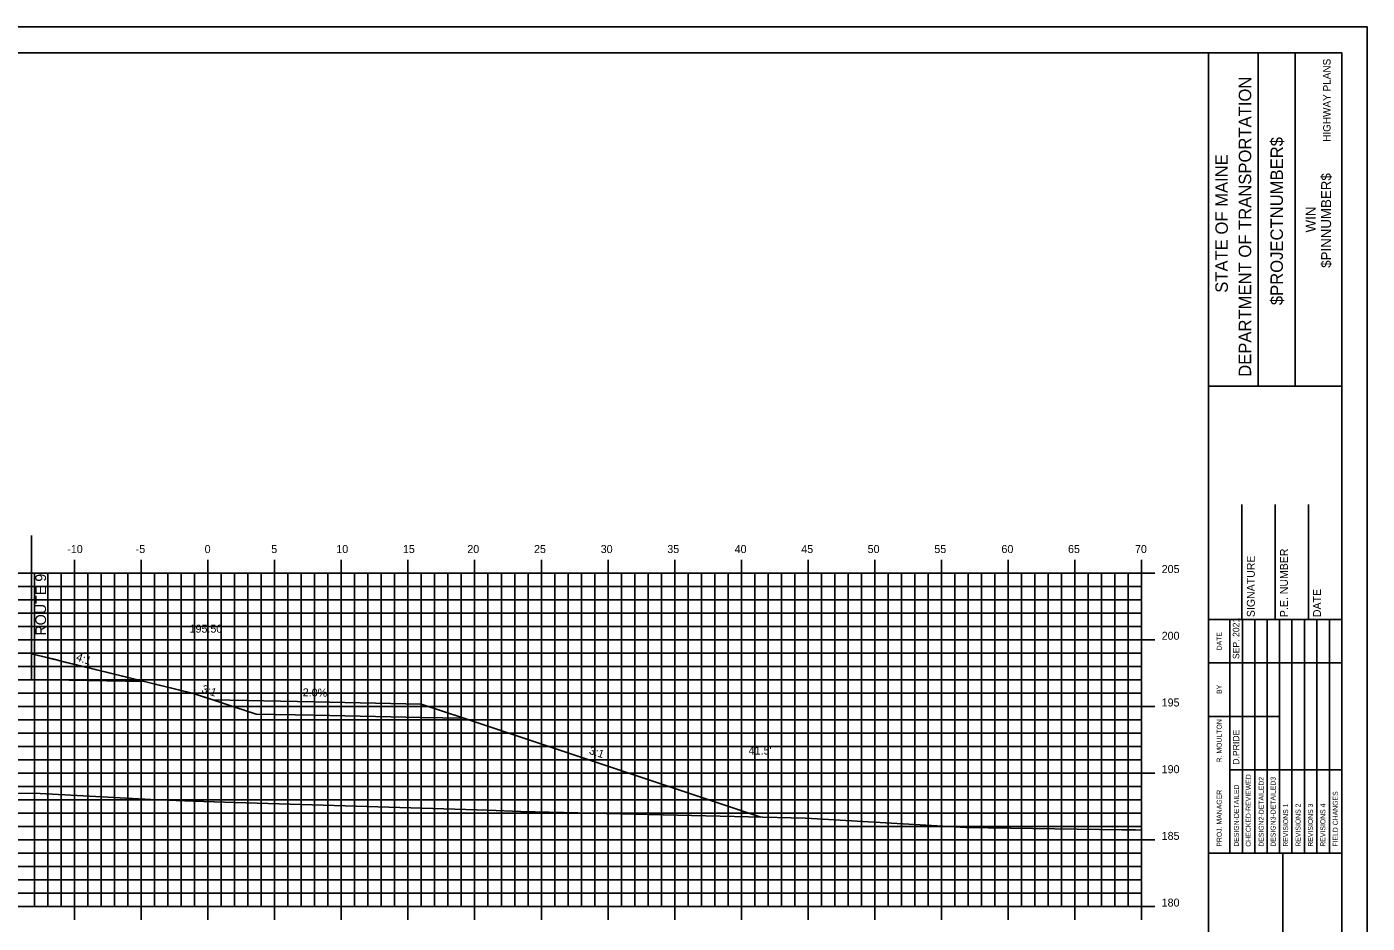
# Model space of a CAD drawing. Extents: x 1723518 to 1723690, y 459560 to 459670.
# Drawn here: x 1723587.4 to 1723687.9, y 459602.4 to 459669.6 of the extents above; entities that cross this region are included whole.
import ezdxf

# ---------------------------------------------------------------- set-up
doc = ezdxf.new("R2010")
doc.units = 0
for name, color, linetype in [('ANNOTATION', 7, 'Continuous'), ('BORDER', 7, 'Continuous'), ('D_Roadway_Centerline', 7, 'Continuous'), ('D_Roadway_Centerline_Text', 7, 'Continuous'), ('D_Roadway_Drive_Gravel', 7, 'Continuous'), ('D_Roadway_Edge_Shoulder', 7, 'Continuous'), ('D_Roadway_SlopeLines', 7, 'Continuous'), ('D_Roadway_SubGrade', 7, 'Continuous'), ('D_Text_Standard', 7, 'Continuous'), ('H_V ANNOTATION', 7, 'Continuous'), ('HIGHWAY_TITLE', 7, 'Continuous'), ('MAJOR', 7, 'Continuous'), ('MINOR', 7, 'Continuous'), ('PLOT BOUNDARY', 7, 'Continuous'), ('S_Roadway_Centerline', 7, 'Continuous')]:
    doc.layers.add(name, color=color, linetype=linetype)

msp = doc.modelspace()

# ---------------------------------------------------------------- linework, layer by layer
msp.add_lwpolyline([(1723601.33, 459619.11), (1723608.96, 459618.95), (1723616.96, 459618.79), (1723620.15, 459617.73), (1723642.42, 459610.31)])
at = {"layer": 'BORDER'}
for p, q in [((1723675.96, 459562.61), (1723675.96, 459667.61)), ((1723679.69, 459642.61), (1723679.69, 459667.61)), ((1723682.48, 459642.61), (1723682.48, 459667.61)), ((1723675.96, 459642.61), (1723685.96, 459642.61)), ((1723678.46, 459625.12), (1723678.46, 459633.76)), ((1723680.96, 459625.12), (1723680.96, 459633.76)), ((1723683.46, 459625.12), (1723683.46, 459633.76)), ((1723675.96, 459625.12), (1723685.96, 459625.12)), ((1723675.96, 459607.62), (1723685.96, 459607.62)), ((1723681.55, 459572.62), (1723681.55, 459607.62))]:
    msp.add_line(p, q, dxfattribs=at)
msp.add_lwpolyline([(1723525.96, 459562.61), (1723685.96, 459562.61), (1723685.96, 459667.61), (1723525.96, 459667.61)], close=True, dxfattribs=at)
for points in [[(1723677.58, 459621.87), (1723677.58, 459625.12)], [(1723678.51, 459607.62), (1723678.51, 459625.12)], [(1723679.44, 459625.12), (1723679.44, 459607.62)], [(1723680.37, 459607.62), (1723680.37, 459625.12)], [(1723681.3, 459607.62), (1723681.3, 459625.12)], [(1723682.23, 459607.62), (1723682.23, 459625.12)], [(1723683.17, 459607.62), (1723683.17, 459625.12)], [(1723684.1, 459607.62), (1723684.1, 459625.12)], [(1723685.03, 459607.62), (1723685.03, 459625.12)], [(1723677.58, 459607.62), (1723677.58, 459624.41)], [(1723675.96, 459621.87), (1723685.96, 459621.87)], [(1723675.96, 459617.87), (1723677.58, 459617.87)], [(1723677.58, 459617.87), (1723681.3, 459617.87)], [(1723677.58, 459613.87), (1723685.96, 459613.87)]]:
    msp.add_lwpolyline(points, dxfattribs=at)
at = {"layer": 'D_Roadway_Centerline'}
msp.add_lwpolyline([(1723587.73, 459622.56), (1723589.53, 459622.12), (1723590.03, 459621.99), (1723591.38, 459621.66), (1723595.59, 459620.63), (1723595.92, 459620.55), (1723596.2, 459620.48), (1723599.04, 459619.79), (1723599.88, 459619.58), (1723601.33, 459619.11)], dxfattribs=at)
at = {"layer": 'D_Roadway_Drive_Gravel'}
msp.add_lwpolyline([(1723601.33, 459619.11), (1723608.96, 459618.95), (1723616.96, 459618.79), (1723620.15, 459617.73), (1723616.96, 459617.79), (1723608.96, 459617.95), (1723604.59, 459618.04)], dxfattribs=at)
at = {"layer": 'D_Roadway_Edge_Shoulder'}
msp.add_line((1723587.73, 459622.56), (1723587.73, 459622.31), dxfattribs=at)
msp.add_line((1723587.73, 459622.56), (1723587.73, 459622.31), dxfattribs=at)
at = {"layer": 'D_Roadway_SlopeLines'}
for points in [[(1723587.73, 459622.56), (1723599.88, 459619.58), (1723604.59, 459618.04)], [(1723587.73, 459622.56), (1723599.88, 459619.58), (1723604.59, 459618.04)], [(1723587.73, 459622.56), (1723599.88, 459619.58), (1723604.59, 459618.04)], [(1723587.73, 459622.56), (1723599.88, 459619.58), (1723604.59, 459618.04)], [(1723587.73, 459622.56), (1723599.88, 459619.58), (1723604.59, 459618.04)], [(1723587.73, 459622.56), (1723599.88, 459619.58), (1723604.59, 459618.04)], [(1723587.73, 459622.56), (1723599.88, 459619.58), (1723604.59, 459618.04)], [(1723616.96, 459618.79), (1723620.15, 459617.73), (1723642.42, 459610.31)]]:
    msp.add_lwpolyline(points, dxfattribs=at)
at = {"layer": 'D_Roadway_SubGrade'}
msp.add_line((1723587.73, 459631.42), (1723587.73, 459620.63), dxfattribs=at)
msp.add_lwpolyline([(1723587.73, 459622.31), (1723587.73, 459622.56), (1723596.2, 459620.48), (1723587.73, 459620.63)], dxfattribs=at)
msp.add_lwpolyline([(1723587.73, 459622.31), (1723587.73, 459622.56), (1723596.2, 459620.48), (1723587.73, 459620.63)], dxfattribs=at)
msp.add_lwpolyline([(1723587.73, 459622.31), (1723587.73, 459622.56), (1723596.2, 459620.48), (1723587.73, 459620.63)], dxfattribs=at)
msp.add_lwpolyline([(1723587.73, 459622.31), (1723587.73, 459622.56), (1723596.2, 459620.48), (1723587.73, 459620.63)], dxfattribs=at)
at = {"layer": 'MAJOR'}
for p, q in [((1723590.96, 459629.61), (1723590.96, 459628.61)), ((1723595.96, 459629.61), (1723595.96, 459628.61)), ((1723600.96, 459629.61), (1723600.96, 459628.61)), ((1723605.96, 459629.61), (1723605.96, 459628.61)), ((1723610.96, 459629.61), (1723610.96, 459628.61)), ((1723615.96, 459629.61), (1723615.96, 459628.61)), ((1723620.96, 459629.61), (1723620.96, 459628.61)), ((1723625.96, 459629.61), (1723625.96, 459628.61)), ((1723630.96, 459629.61), (1723630.96, 459628.61)), ((1723635.96, 459629.61), (1723635.96, 459628.61)), ((1723640.96, 459629.61), (1723640.96, 459628.61)), ((1723645.96, 459629.61), (1723645.96, 459628.61)), ((1723650.96, 459629.61), (1723650.96, 459628.61)), ((1723655.96, 459629.61), (1723655.96, 459628.61)), ((1723660.96, 459629.61), (1723660.96, 459628.61)), ((1723665.96, 459629.61), (1723665.96, 459628.61)), ((1723670.96, 459629.61), (1723670.96, 459628.61)), ((1723530.96, 459628.61), (1723670.96, 459628.61)), ((1723530.96, 459628.61), (1723670.96, 459628.61)), ((1723590.96, 459603.61), (1723590.96, 459628.61)), ((1723595.96, 459603.61), (1723595.96, 459628.61)), ((1723600.96, 459603.61), (1723600.96, 459628.61)), ((1723605.96, 459603.61), (1723605.96, 459628.61)), ((1723610.96, 459603.61), (1723610.96, 459628.61)), ((1723615.96, 459603.61), (1723615.96, 459628.61)), ((1723620.96, 459603.61), (1723620.96, 459628.61)), ((1723625.96, 459603.61), (1723625.96, 459628.61)), ((1723630.96, 459603.61), (1723630.96, 459628.61)), ((1723635.96, 459603.61), (1723635.96, 459628.61)), ((1723640.96, 459603.61), (1723640.96, 459628.61)), ((1723645.96, 459603.61), (1723645.96, 459628.61)), ((1723650.96, 459603.61), (1723650.96, 459628.61)), ((1723655.96, 459603.61), (1723655.96, 459628.61)), ((1723660.96, 459603.61), (1723660.96, 459628.61)), ((1723665.96, 459603.61), (1723665.96, 459628.61)), ((1723671.96, 459628.61), (1723669.96, 459628.61)), ((1723670.96, 459603.61), (1723670.96, 459628.61)), ((1723670.96, 459603.61), (1723670.96, 459628.61)), ((1723530.96, 459623.61), (1723670.96, 459623.61)), ((1723671.96, 459623.61), (1723669.96, 459623.61)), ((1723530.96, 459618.61), (1723670.96, 459618.61)), ((1723671.96, 459618.61), (1723669.96, 459618.61)), ((1723530.96, 459613.61), (1723670.96, 459613.61)), ((1723671.96, 459613.61), (1723669.96, 459613.61)), ((1723530.96, 459608.61), (1723670.96, 459608.61)), ((1723671.96, 459608.61), (1723669.96, 459608.61)), ((1723530.96, 459603.61), (1723670.96, 459603.61)), ((1723530.96, 459603.61), (1723670.96, 459603.61)), ((1723590.96, 459602.61), (1723590.96, 459603.61)), ((1723595.96, 459602.61), (1723595.96, 459603.61)), ((1723600.96, 459602.61), (1723600.96, 459603.61)), ((1723605.96, 459602.61), (1723605.96, 459603.61)), ((1723610.96, 459602.61), (1723610.96, 459603.61)), ((1723615.96, 459602.61), (1723615.96, 459603.61)), ((1723620.96, 459602.61), (1723620.96, 459603.61)), ((1723625.96, 459602.61), (1723625.96, 459603.61)), ((1723630.96, 459602.61), (1723630.96, 459603.61)), ((1723635.96, 459602.61), (1723635.96, 459603.61)), ((1723640.96, 459602.61), (1723640.96, 459603.61)), ((1723645.96, 459602.61), (1723645.96, 459603.61)), ((1723650.96, 459602.61), (1723650.96, 459603.61)), ((1723655.96, 459602.61), (1723655.96, 459603.61)), ((1723660.96, 459602.61), (1723660.96, 459603.61)), ((1723665.96, 459602.61), (1723665.96, 459603.61)), ((1723671.96, 459603.61), (1723669.96, 459603.61)), ((1723670.96, 459602.61), (1723670.96, 459603.61))]:
    msp.add_line(p, q, dxfattribs=at)
at = {"layer": 'MINOR'}
for p, q in [((1723587.96, 459603.61), (1723587.96, 459628.61)), ((1723588.96, 459603.61), (1723588.96, 459628.61)), ((1723589.96, 459603.61), (1723589.96, 459628.61)), ((1723591.96, 459603.61), (1723591.96, 459628.61)), ((1723592.96, 459603.61), (1723592.96, 459628.61)), ((1723593.96, 459603.61), (1723593.96, 459628.61)), ((1723594.96, 459603.61), (1723594.96, 459628.61)), ((1723596.96, 459603.61), (1723596.96, 459628.61)), ((1723597.96, 459603.61), (1723597.96, 459628.61)), ((1723598.96, 459603.61), (1723598.96, 459628.61)), ((1723599.96, 459603.61), (1723599.96, 459628.61)), ((1723601.96, 459603.61), (1723601.96, 459628.61)), ((1723602.96, 459603.61), (1723602.96, 459628.61)), ((1723603.96, 459603.61), (1723603.96, 459628.61)), ((1723604.96, 459603.61), (1723604.96, 459628.61)), ((1723606.96, 459603.61), (1723606.96, 459628.61)), ((1723607.96, 459603.61), (1723607.96, 459628.61)), ((1723608.96, 459603.61), (1723608.96, 459628.61)), ((1723609.96, 459603.61), (1723609.96, 459628.61)), ((1723611.96, 459603.61), (1723611.96, 459628.61)), ((1723612.96, 459603.61), (1723612.96, 459628.61)), ((1723613.96, 459603.61), (1723613.96, 459628.61)), ((1723614.96, 459603.61), (1723614.96, 459628.61)), ((1723616.96, 459603.61), (1723616.96, 459628.61)), ((1723617.96, 459603.61), (1723617.96, 459628.61)), ((1723618.96, 459603.61), (1723618.96, 459628.61)), ((1723619.96, 459603.61), (1723619.96, 459628.61)), ((1723621.96, 459603.61), (1723621.96, 459628.61)), ((1723622.96, 459603.61), (1723622.96, 459628.61)), ((1723623.96, 459603.61), (1723623.96, 459628.61)), ((1723624.96, 459603.61), (1723624.96, 459628.61)), ((1723626.96, 459603.61), (1723626.96, 459628.61)), ((1723627.96, 459603.61), (1723627.96, 459628.61)), ((1723628.96, 459603.61), (1723628.96, 459628.61)), ((1723629.96, 459603.61), (1723629.96, 459628.61)), ((1723631.96, 459603.61), (1723631.96, 459628.61)), ((1723632.96, 459603.61), (1723632.96, 459628.61)), ((1723633.96, 459603.61), (1723633.96, 459628.61)), ((1723634.96, 459603.61), (1723634.96, 459628.61)), ((1723636.96, 459603.61), (1723636.96, 459628.61)), ((1723637.96, 459603.61), (1723637.96, 459628.61)), ((1723638.96, 459603.61), (1723638.96, 459628.61)), ((1723639.96, 459603.61), (1723639.96, 459628.61)), ((1723641.96, 459603.61), (1723641.96, 459628.61)), ((1723642.96, 459603.61), (1723642.96, 459628.61)), ((1723643.96, 459603.61), (1723643.96, 459628.61)), ((1723644.96, 459603.61), (1723644.96, 459628.61)), ((1723646.96, 459603.61), (1723646.96, 459628.61)), ((1723647.96, 459603.61), (1723647.96, 459628.61)), ((1723648.96, 459603.61), (1723648.96, 459628.61)), ((1723649.96, 459603.61), (1723649.96, 459628.61)), ((1723651.96, 459603.61), (1723651.96, 459628.61)), ((1723652.96, 459603.61), (1723652.96, 459628.61)), ((1723653.96, 459603.61), (1723653.96, 459628.61)), ((1723654.96, 459603.61), (1723654.96, 459628.61)), ((1723656.96, 459603.61), (1723656.96, 459628.61)), ((1723657.96, 459603.61), (1723657.96, 459628.61)), ((1723658.96, 459603.61), (1723658.96, 459628.61)), ((1723659.96, 459603.61), (1723659.96, 459628.61)), ((1723661.96, 459603.61), (1723661.96, 459628.61)), ((1723662.96, 459603.61), (1723662.96, 459628.61)), ((1723663.96, 459603.61), (1723663.96, 459628.61)), ((1723664.96, 459603.61), (1723664.96, 459628.61)), ((1723666.96, 459603.61), (1723666.96, 459628.61)), ((1723667.96, 459603.61), (1723667.96, 459628.61)), ((1723668.96, 459603.61), (1723668.96, 459628.61)), ((1723669.96, 459603.61), (1723669.96, 459628.61)), ((1723530.96, 459627.61), (1723670.96, 459627.61)), ((1723670.96, 459627.61), (1723669.96, 459627.61)), ((1723530.96, 459626.61), (1723670.96, 459626.61)), ((1723670.96, 459626.61), (1723669.96, 459626.61)), ((1723530.96, 459625.61), (1723670.96, 459625.61)), ((1723670.96, 459625.61), (1723669.96, 459625.61)), ((1723530.96, 459624.61), (1723670.96, 459624.61)), ((1723670.96, 459624.61), (1723669.96, 459624.61)), ((1723530.96, 459622.61), (1723670.96, 459622.61)), ((1723670.96, 459622.61), (1723669.96, 459622.61)), ((1723530.96, 459621.61), (1723670.96, 459621.61)), ((1723670.96, 459621.61), (1723669.96, 459621.61)), ((1723530.96, 459620.61), (1723670.96, 459620.61)), ((1723670.96, 459620.61), (1723669.96, 459620.61)), ((1723530.96, 459619.61), (1723670.96, 459619.61)), ((1723670.96, 459619.61), (1723669.96, 459619.61)), ((1723530.96, 459617.61), (1723670.96, 459617.61)), ((1723670.96, 459617.61), (1723669.96, 459617.61)), ((1723530.96, 459616.61), (1723670.96, 459616.61)), ((1723670.96, 459616.61), (1723669.96, 459616.61)), ((1723530.96, 459615.61), (1723670.96, 459615.61)), ((1723670.96, 459615.61), (1723669.96, 459615.61)), ((1723530.96, 459614.61), (1723670.96, 459614.61)), ((1723670.96, 459614.61), (1723669.96, 459614.61)), ((1723530.96, 459612.61), (1723670.96, 459612.61)), ((1723670.96, 459612.61), (1723669.96, 459612.61)), ((1723530.96, 459611.61), (1723670.96, 459611.61)), ((1723670.96, 459611.61), (1723669.96, 459611.61)), ((1723530.96, 459610.61), (1723670.96, 459610.61)), ((1723670.96, 459610.61), (1723669.96, 459610.61)), ((1723530.96, 459609.61), (1723670.96, 459609.61)), ((1723670.96, 459609.61), (1723669.96, 459609.61)), ((1723530.96, 459607.61), (1723670.96, 459607.61)), ((1723670.96, 459607.61), (1723669.96, 459607.61)), ((1723530.96, 459606.61), (1723670.96, 459606.61)), ((1723670.96, 459606.61), (1723669.96, 459606.61)), ((1723530.96, 459605.61), (1723670.96, 459605.61)), ((1723670.96, 459605.61), (1723669.96, 459605.61)), ((1723530.96, 459604.61), (1723670.96, 459604.61)), ((1723670.96, 459604.61), (1723669.96, 459604.61))]:
    msp.add_line(p, q, dxfattribs=at)
at = {"layer": 'PLOT BOUNDARY'}
msp.add_lwpolyline([(1723517.87, 459559.55), (1723687.87, 459559.55), (1723687.87, 459669.55), (1723517.87, 459669.55)], close=True, dxfattribs=at)
at = {"layer": 'S_Roadway_Centerline'}
msp.add_lwpolyline([(1723530.96, 459613.18), (1723536.86, 459613.13), (1723547.76, 459612.91), (1723558.35, 459612.59), (1723571.57, 459612.33), (1723580, 459612.19), (1723588.4, 459612.08), (1723596.68, 459611.63), (1723599.86, 459611.51), (1723603.01, 459611.42), (1723621.96, 459610.85), (1723624.42, 459610.74), (1723645.75, 459610.23), (1723646.2, 459610.21), (1723657.78, 459609.53), (1723669.48, 459609.37), (1723670.49, 459609.36), (1723670.96, 459609.33)], dxfattribs=at)

# ---------------------------------------------------------------- texts
at = {"layer": 'ANNOTATION'}
for s, height, rotation, p in [('ROUTE 9', 0.8, 90, (1723588.83, 459623.92)), ('4:1', 0.6, 341.5651, (1723591.04, 459622.07)), ('3:1', 0.6, 341.5651, (1723600.44, 459619.69)), ('-2.0%', 0.6, 358.8542, (1723607.8, 459619.38)), ('3:1', 0.6, 341.5651, (1723629.49, 459615.07))]:
    msp.add_text(s, height=height, rotation=rotation, dxfattribs=at).set_placement(p)
at = {"layer": 'BORDER'}
for s, height, p in [('DEPARTMENT OF TRANSPORTATION', 0.9318, (1723679.17, 459643.32)), ('$PROJECTNUMBER$', 0.9318, (1723681.55, 459648.69)), ('STATE OF MAINE', 0.9318, (1723677.42, 459649.62)), ('$PINNUMBER$', 0.7453, (1723685.16, 459651.49)), ('WIN', 0.745, (1723684, 459654.14)), ('P.E. NUMBER', 0.5906, (1723681.92, 459625.31)), ('SIGNATURE', 0.591, (1723679.44, 459625.31)), ('DATE', 0.591, (1723684.4, 459625.31)), ('SEP. 2021', 0.485, (1723678.28, 459622.16)), ('DATE', 0.371, (1723676.96, 459622.82)), ('BY', 0.371, (1723676.96, 459619.55)), ('R. MOULTON', 0.373, (1723676.96, 459614.42)), ('D.PRIDE', 0.485, (1723678.28, 459614.24)), ('CHECKED-REVIEWED', 0.3727, (1723679.14, 459608.1)), ('DESIGN2-DETAILED2', 0.3727, (1723680.11, 459608.1)), ('DESIGN3-DETAILED3', 0.3727, (1723681, 459608.1)), ('PROJ. MANAGER', 0.3727, (1723676.96, 459608.1)), ('DESIGN-DETAILED', 0.3727, (1723678.25, 459608.1)), ('FIELD CHANGES', 0.3727, (1723685.66, 459608.1)), ('REVISIONS 1', 0.3727, (1723681.94, 459608.1)), ('REVISIONS 2', 0.3727, (1723682.87, 459608.1)), ('REVISIONS 3', 0.3727, (1723683.8, 459608.1)), ('REVISIONS 4', 0.3727, (1723684.73, 459608.1))]:
    msp.add_text(s, height=height, rotation=90, dxfattribs=at).set_placement(p)
at = {"layer": 'D_Roadway_Centerline_Text'}
msp.add_text('195.50', height=0.6, dxfattribs=at).set_placement((1723599.59, 459624.14))
at = {"layer": 'D_Text_Standard'}
msp.add_text("41.5'", height=0.6, dxfattribs=at).set_placement((1723641.5, 459615.01))
at = {"layer": 'H_V ANNOTATION'}
for s, p in [('-10', (1723590.42, 459630.11)), ('-5', (1723595.55, 459630.11)), ('0', (1723600.72, 459630.11)), ('5', (1723605.71, 459630.11)), ('10', (1723610.59, 459630.11)), ('15', (1723615.58, 459630.11)), ('20', (1723620.41, 459630.11)), ('25', (1723625.41, 459630.11)), ('30', (1723630.41, 459630.11)), ('35', (1723635.4, 459630.11)), ('40', (1723640.45, 459630.11)), ('45', (1723645.44, 459630.11)), ('50', (1723650.42, 459630.11)), ('55', (1723655.42, 459630.11)), ('60', (1723660.45, 459630.11)), ('65', (1723665.44, 459630.11)), ('70', (1723670.46, 459630.11)), ('205', (1723672.46, 459628.61)), ('200', (1723672.46, 459623.61)), ('195', (1723672.46, 459618.61)), ('190', (1723672.46, 459613.61)), ('185', (1723672.46, 459608.61)), ('180', (1723672.46, 459603.61))]:
    msp.add_text(s, height=0.6, dxfattribs=at).set_placement(p)
at = {"layer": 'HIGHWAY_TITLE'}
msp.add_text('HIGHWAY PLANS', height=0.559, rotation=90, dxfattribs=at).set_placement((1723685.12, 459660.93))

doc.saveas('drawing.dxf')
